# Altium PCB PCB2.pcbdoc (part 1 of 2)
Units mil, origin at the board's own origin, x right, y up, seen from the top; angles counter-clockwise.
Board outline 3822.51 x 2229.86 mil, 2 copper layers (Top Layer, Bottom Layer); 117 components, 92 nets, 474 pads, 260 vias.
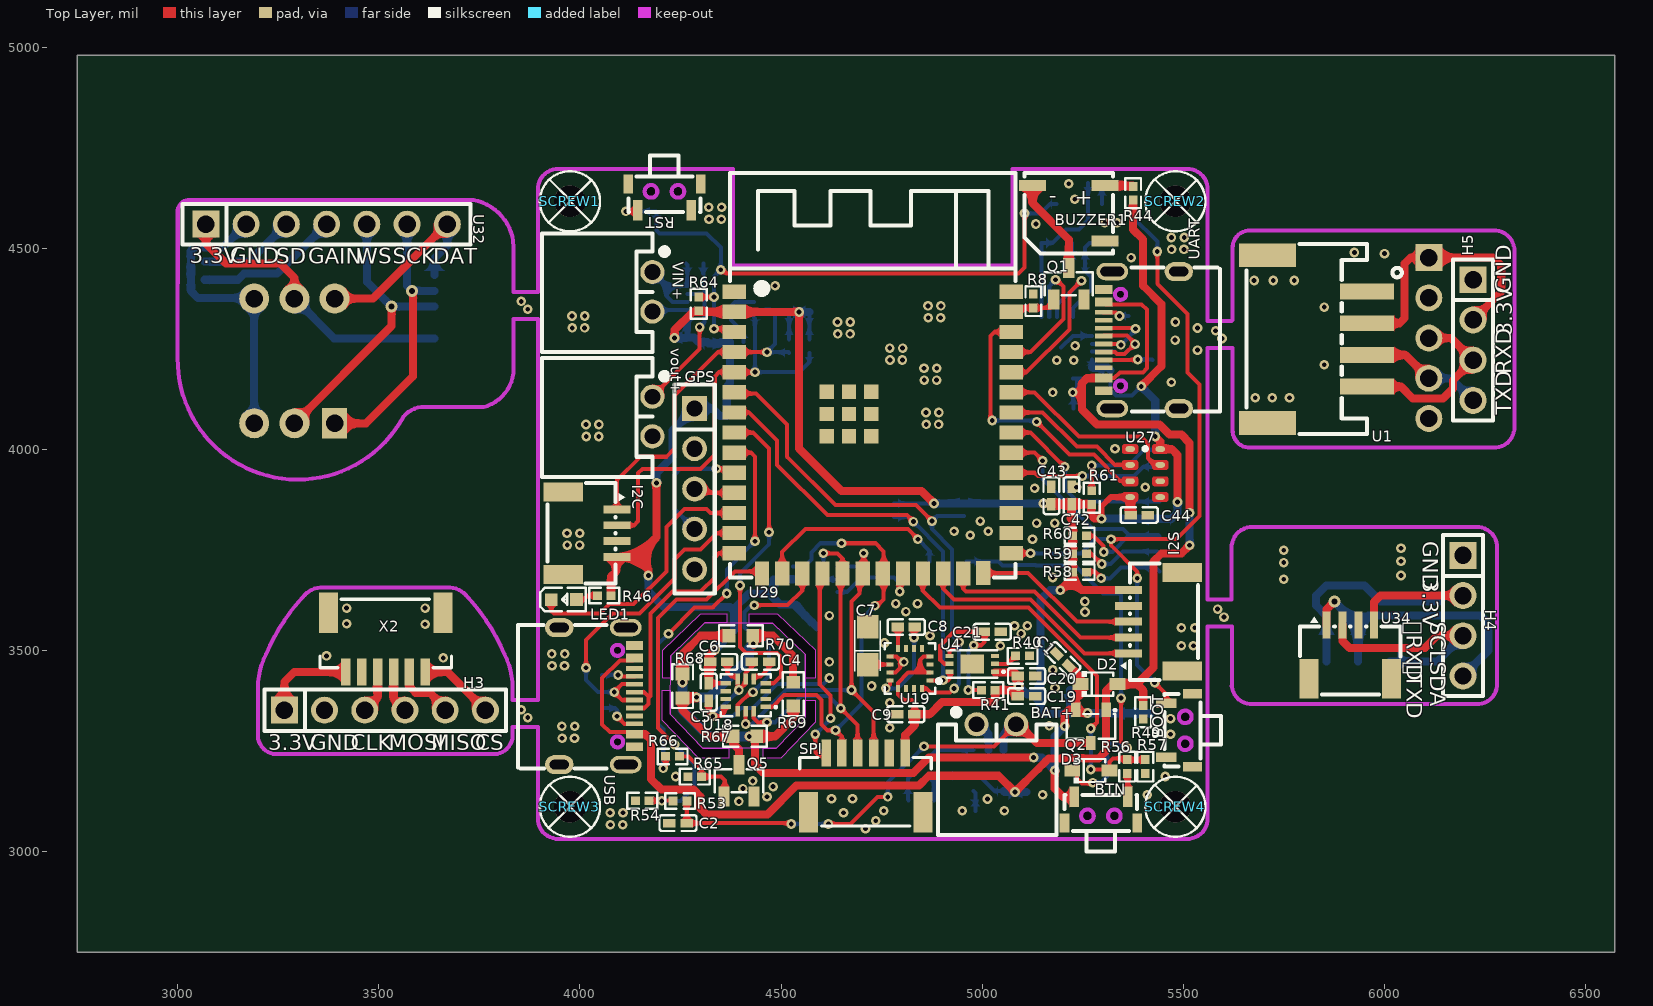
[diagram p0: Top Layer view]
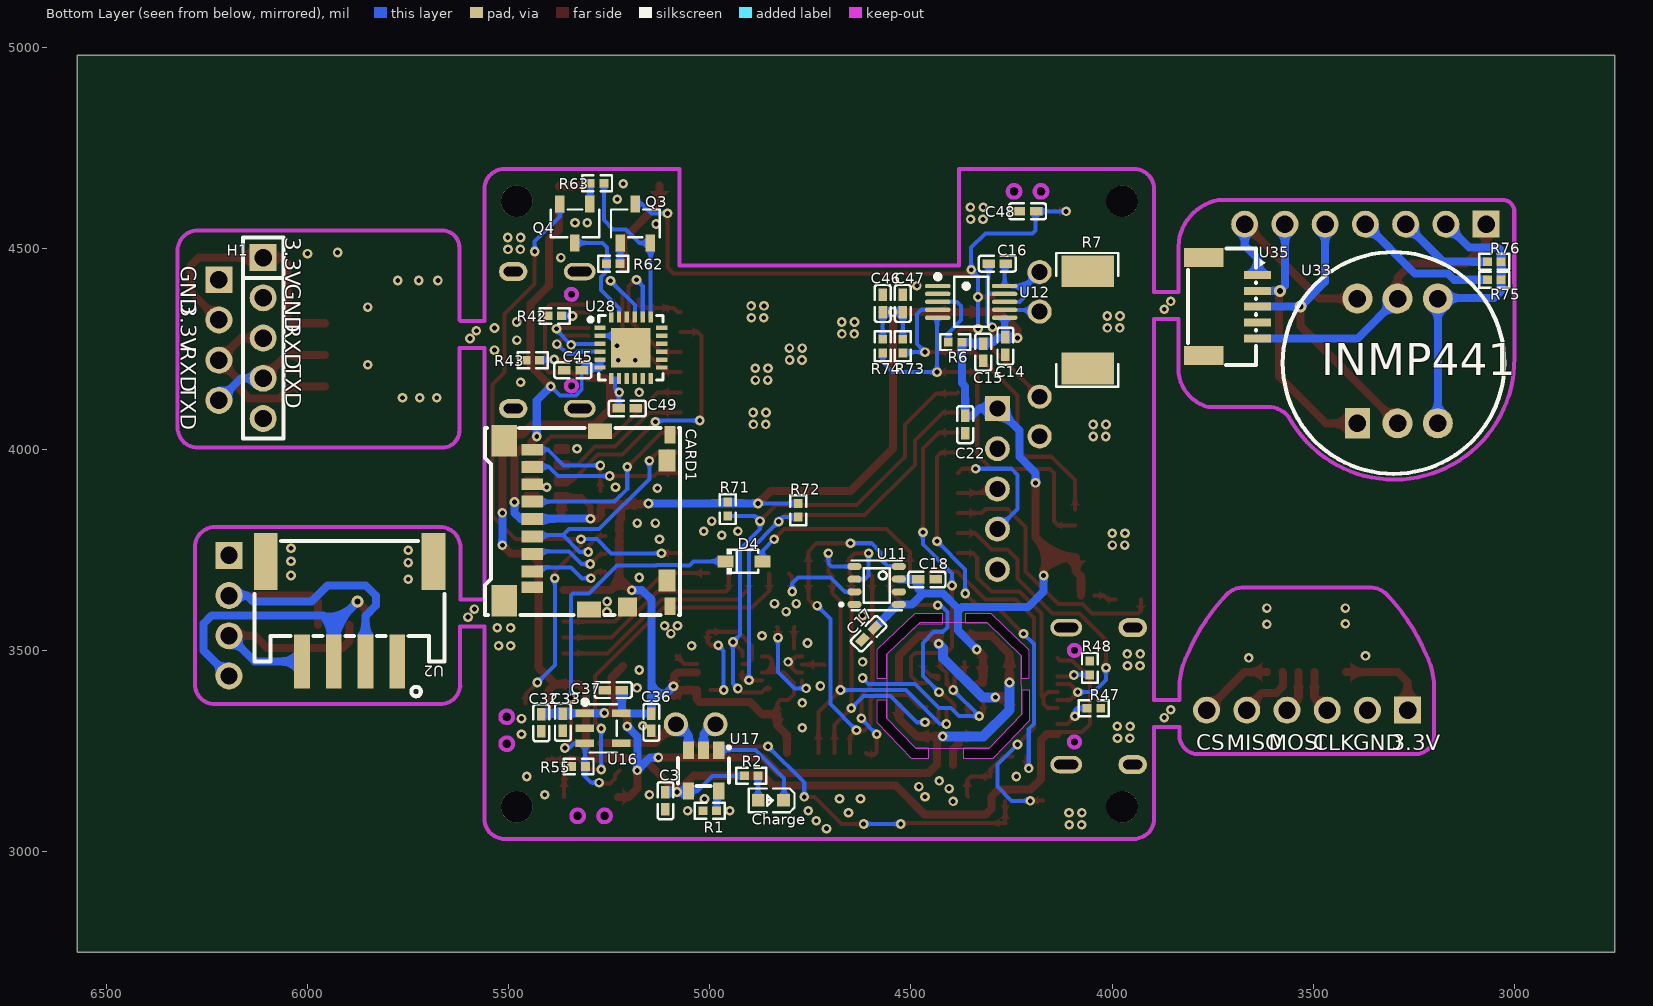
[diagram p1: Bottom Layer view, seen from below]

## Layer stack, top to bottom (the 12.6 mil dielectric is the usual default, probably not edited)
Top Layer: signal copper (thickness not stored)
Dielectric: dielectric 12.6, FR-4, Dk 4.8
Bottom Layer: signal copper (thickness not stored)

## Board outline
6572.51,2750 2750,2750 2750,4979.86 6572.51,4979.86
cut-out: 4365.02,3568.87 4310.07,3568.87 4225.02,3486.31 4225.02,3431.5 4205.12,3431.5 4205.12,3501.11 4300.16,3591.5 4365.02,3591.5
cut-out: 4224.93,3401.5 4224.93,3341.84 4305.21,3256.5 4370.02,3256.5 4370.02,3231.6 4295.16,3231.6 4205.02,3326.38 4205.02,3401.5
cut-out: 4455.12,3256.41 4487.39,3256.41 4560.02,3331.5 4560.02,3376.05 4585.15,3376.05 4585.15,3321.59 4499.51,3231.5 4455.12,3231.5
cut-out: 4560.23,3431.13 4560.23,3491.05 4480.39,3566.4 4420.47,3566.4 4420.47,3591.52 4490.47,3591.52 4585.02,3501.46 4585.02,3431.13

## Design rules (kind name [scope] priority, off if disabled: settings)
Clearance copperThickness1oz [All] p1: gap=7 ignorepadtopadclearanceinfootprint=FALSE except(4: Track-Track; 6: Track-SMDPad SMDPad-SMDPad Track-THPad SMDPad-THPad THPad-THPad Track-Via SMDPad-Via THPad-Via Via-Via SMDPad-Fill THPad-Fill Via-Fill Fill-Fill Track-Region SMDPad-Region THPad-Region Via-Region Region-Region Track-Poly SMDPad-Poly THPad-Poly Via-Poly Fill-Poly Region-Poly Poly-Poly Track-Text SMDPad-Text THPad-Text Via-Text Fill-Text Region-Text Poly-Text Text-Text; 6.9: Track-Hole SMDPad-Hole THPad-Hole Via-Hole Fill-Hole Region-Hole Poly-Hole Text-Hole Sheet-Hole; 11.8: Track-Fill Fill-Region Track-Sheet SMDPad-Sheet THPad-Sheet Via-Sheet Fill-Sheet Region-Sheet Poly-Sheet Text-Sheet)
Clearance copperThickness2oz [All] p1: gap=7 ignorepadtopadclearanceinfootprint=FALSE except(6: Track-SMDPad SMDPad-SMDPad Track-THPad SMDPad-THPad THPad-THPad Track-Via SMDPad-Via THPad-Via Via-Via SMDPad-Fill THPad-Fill Via-Fill Fill-Fill Track-Region SMDPad-Region THPad-Region Via-Region Region-Region Track-Poly SMDPad-Poly THPad-Poly Via-Poly Fill-Poly Region-Poly Poly-Poly Track-Text SMDPad-Text THPad-Text Via-Text Fill-Text Region-Text Poly-Text Text-Text; 6.9: Track-Hole SMDPad-Hole THPad-Hole Via-Hole Fill-Hole Region-Hole Poly-Hole Text-Hole Sheet-Hole; 8: Track-Track; 11.8: Track-Fill Fill-Region Track-Sheet SMDPad-Sheet THPad-Sheet Via-Sheet Fill-Sheet Region-Sheet Poly-Sheet Text-Sheet)
DiffPairsRouting differentialPair [All] p1: maxuncoupledlength=10 maxlimit=5.9843 mostfreqgap=5.9843 toplayer_minwidth=5 toplayer_prefwidth=10 toplayer_maxwidth=100 bottomlayer_minwidth=5 bottomlayer_prefwidth=10 bottomlayer_maxwidth=100
PasteMaskExpansion pasteMaskExpansion [All] p1:
PlaneConnect innerPlane [All] p1: planeconnectstyle=Relief reliefexpansion=20 reliefentries=4 reliefconductorwidth=10 reliefairgap=10
PolygonConnect copperRegion [All] p1: connectstyle=Relief reliefentries=4 reliefconductorwidth=10 polygonreliefangle="90 Angle" airgapwidth=10
PolygonConnect copperRegion1 [All] p1: connectstyle=Direct reliefentries=4 reliefconductorwidth=10 polygonreliefangle="90 Angle" airgapwidth=10
RoutingVias viaSize [All] p1: viastyle="Through Hole" holewidth=12.0078 minholewidth=11.811 maxholewidth=248.0314 width=24.0158 minwidth=19.685 maxwidth=393.7008
SolderMaskExpansion solderMaskExpansion [All] p1: useseparateexpansions=TRUE expansion=2.0079 expansionbottom=2.0079
Width copperThickness1oz [All] p1: maxlimit=100 minlimit=5 preferedwidth=10
Width copperThickness2oz [All] p1: maxlimit=100 minlimit=8 preferedwidth=10

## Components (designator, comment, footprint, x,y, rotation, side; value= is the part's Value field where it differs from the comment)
BAT+ "XH2.54-2P_H弯针插座" CONN-TH_2P-P2.5_XH2.54-2P_H 5035.02,3316.5 r0 top
BOOT "1TS003B-1800-3500A-CT" SW-SMD_1TS003B-XXXX-3500A-CT#1 5490.02,3301.5 r270 top
BTN "1TS003B-1800-3500A-CT" SW-SMD_1TS003B-XXXX-3500A-CT#2 5294.94,3103.36 r180 top
BUZZER1 "MLT-5020" BUZ-SMD_L5.0-W5.5-P4.60 5215.02,4586.5 r180 top
C1 "CL05A106MQ5NUNC" C0402 5200.02,3476.5 r315 top
C2 "CL05A106MQ5NUNC" C0402 4243.64,3070.81 r180 top
C3 "CL05A106MQ5NUNC" C0402 5110.02,3126.5 r90 bottom
C4 "CC0402KRX7R7BB103" C0402 4448.64,3472.02 r180 top
C5 "CC0402KRX7R7BB104" C0402 4320.02,3396.5 r90 top
C6 "GRM155R61E225KE11D" C0402 4345.02,3471.5 r180 top
C7 "TAJA475K016RNJ" CASE-A_3216 4715.02,3511.5 r90 top
C8 "CL05B224KO5NNNC" C0402 4810.89,3558.36 r0 top
C9 "CC0402KRX7R7BB104" C0402 4810.02,3341.5 r0 top
C14 "CC0402KRX7R7BB104" C0402 4265.02,4256.5 r90 bottom
C15 "C1005X5R105KCTS" C0402 4320.02,4241.5 r90 bottom
C16 "CC0402KRX7R7BB104" C0402 4285.02,4461.5 r180 bottom
C17 "CC0402KRX7R7BB104" C0402 4605.02,3541.5 r135 bottom
C18 "C1005X5R105KCTS" C0402 4460.02,3676.5 r0 bottom
C19 "CC0402KRX7R7BB104" C0402 5110.02,3386.5 r180 top
C20 "C1005X5R105KCTS" C0402 5110.02,3436.5 r180 top
C21 "CC0402KRX7R7BB104" C0402 5025.02,3546.5 r180 top
C22 "CC0402KRX7R7BB104" C0402 4365.02,4061.5 r90 bottom
C32 "CL05A106MQ5NUNC" C0402 5418.56,3320.04 r90 bottom
C33 "CC0402KRX7R7BB104" C0402 5365.02,3321.5 r90 bottom
C36 "CL05A106MQ5NUNC" C0402 5145.02,3321.5 r90 bottom
C37 "CC0402KRX7R7BB104" C0402 5240.02,3401.5 r180 bottom
C42 "0603B104K500NT" C0402 5221.88,3884.9 r270 top
C43 "C1005X5R105KCTS" C0402 5171.88,3884.9 r270 top
C44 "CC0402KRX7R7BB104" C0402 5390.02,3836.5 r0 top
C45 "0603B104K500NT" C0402 5340.02,4196.5 r0 bottom
C46 "CC0402KRX7R7BB104" C0402 4570.02,4362.5 r90 bottom
C47 "C1005X5R105KCTS" C0402 4520.02,4362.5 r90 bottom
C48 "C1005X5R105KCTS" C0402 4210.02,4591.5 r0 bottom
C49 "CC0402KRX7R7BB104" C0402 5205.02,4101.5 r0 bottom
CARD1 "TF-110" TF-SMD_TF-110 5304.85,3823.2 r270 bottom
Charge "XL-1608SURC-06" LED0603-RD_RED 4848.02,3127.5 r0 bottom
D2 "1N5819WS_C191023" SOD-323_L1.8-W1.3-LS2.5-RD 5290.02,3416.5 r0 top
D3 "1N5819WS_C191023" SOD-323_L1.8-W1.3-LS2.5-RD 5270.02,3201.5 r0 top
D4 "1N5819WS_C191023" SOD-323_L1.8-W1.3-LS2.5-RD 4915.02,3721.5 r180 bottom
GPS "2.54-1*5P母" HDR-TH_5P-P2.54-V-F 4285.02,3901.5 r270 top
H1 "KH-2.54PH180-1X5P-L11.5" HDR-TH_5P-P2.54-V-M 6109.98,4276.54 r270 bottom
H3 "PZ254V-11-06P" HDR-TH_6P-P2.54-V-M 3515.02,3351.5 r0 top
H4 "PZ254V-11-04P" HDR-TH_4P-P2.54-V-M 6195.02,3586.5 r270 top
H5 "PZ254V-11-04P" HDR-TH_4P-P2.54-V-M 6219.98,4271.54 r270 top
I2C "ZX-SH1.0-4PWT" CONN-SMD_4P-P1.00_MEGASTAR_ZX-SH1.0-4PWT 4025.02,3791.5 r270 top
I2S "ZX-SH1.0-5PWT" CONN-SMD_5P-P1.00_MEGASTAR_ZX-SH1.0-5PWT 5430.02,3571.5 r90 top
LED1 "XL-1608SURC-06" LED0603-RD_RED 3960.02,3626.5 r0 top
Q1 "SI2302-HXY" SOT-23-3_L2.9-W1.3-P1.90-LS2.4-BR 5215.02,4411.5 r270 top
Q2 "AO3401_C727156" SOT-23-3_L2.9-W1.4-P1.90-LS2.6-BR 5270.02,3311.5 r90 top
Q3 "S8050_C181158" SOT-23-3_L2.9-W1.6-P1.90-LS2.8-BR 5185.02,4561.5 r270 bottom
Q4 "S8050_C181158" SOT-23-3_L2.9-W1.6-P1.90-LS2.8-BR 5335.02,4561.5 r90 bottom
Q5 "AO3400A_C20917" SOT-23-3_L2.9-W1.3-P1.90-LS2.4-BR 4395.02,3176.5 r270 top
R1 "0402WGF2001TCE" R0402 5000.02,3101.5 r0 bottom
R2 "0402WGF3300TCE" R0402 4897.02,3188.5 r180 bottom
R6 "RTT02472JTH" R0402 4390.02,4266.5 r0 bottom
R7 "LRAN25EJER005" RES-SMD_L6.4-W3.2-R2512 4060.02,4321.5 r90 bottom
R8 "RC0402FR-0710KL" R0402 5127.02,4368.5 r270 top
R40 "RC0402FR-0710KL" R0402 5100.02,3486.5 r180 top
R41 "0402WGF1001TCE" R0402 5015.02,3401.5 r0 top
R42 "0402WGF5101TCE" R0402 5385.02,4331.5 r0 bottom
R43 "0402WGF5101TCE" R0402 5440.02,4221.5 r0 bottom
R44 "0402WGF220KTCE" R0402 5375.02,4636.5 r270 top
R46 "0402WGF1001TCE" R0402 4060.02,3636.5 r0 top
R47 "0402WGF5101TCE" R0402 4045.02,3356.5 r180 bottom
R48 "0402WGF5101TCE" R0402 4055.02,3456.5 r90 bottom
R49 "0402WGF2003TCE" R0402 5400.02,3346.5 r90 top
R53 "0402WGF5103TCE" R0402 4248.64,3125.81 r0 top
R54 "0402WGF5103TCE" R0402 4155.02,3126.5 r0 top
R55 "RC0402FR-0710KL" R0402 5326.02,3211.5 r180 bottom
R56 "0402WGF2001TCE" R0402 5360.02,3211.5 r90 top
R57 "0402WGF5101TCE" R0402 5405.02,3211.5 r270 top
R58 "RC0402FR-0710KL" R0402 5241.88,3694.9 r0 top
R59 "RC0402FR-0710KL" R0402 5241.88,3739.9 r0 top
R60 "RC0402FR-0710KL" R0402 5241.88,3784.9 r0 top
R61 "RC0402FR-0710KL" R0402 5271.88,3879.9 r90 top
R62 "RC0402FR-0710KL" R0402 5240.02,4461.5 r180 bottom
R63 "RC0402FR-0710KL" R0402 5280.02,4661.5 r0 bottom
R64 "RC0402FR-0710KL" R0402 4295.02,4361.5 r90 top
R65 "RC0402FR-0710KL" R0402 4285.02,3186.5 r180 top
R66 "0402WGJ0101TCE" R0402 4230.02,3236.5 r0 top
R67 "0603WAF510JT5E" R0603 4410.02,3286.5 r0 top
R68 "0603WAF510JT5E" R0603 4255.02,3411.5 r90 top
R69 "0603WAF510JT5E" R0603 4530.02,3391.5 r270 top
R70 "0603WAF510JT5E" R0603 4400.02,3536.5 r180 top
R71 "0402WGJ0472TCE" R0402 4955.02,3851.5 r90 bottom
R72 "0402WGJ0472TCE" R0402 4780.02,3848.5 r90 bottom
R73 "0402WGJ0472TCE" R0402 4520.02,4256.5 r270 bottom
R74 "0402WGJ0472TCE" R0402 4570.02,4256.5 r270 bottom
R75 "0402WGF1003TCE" R0402 3050.02,4421.5 r0 bottom
R76 "0402WGF1003TCE" R0402 3050.02,4466.5 r0 bottom
RST "1TS003B-1800-3500A-CT" SW-SMD_1TS003B-XXXX-3500A-CT#2 4210.02,4626.5 r0 top
SCREW1 "M2螺丝" M2螺丝 3975.02,4616.5 r0 top locked
SCREW2 "M2螺丝" M2螺丝 5480.02,4616.5 r0 top locked
SCREW3 "M2螺丝" M2螺丝 3975.02,3111.5 r0 top locked
SCREW4 "M2螺丝" M2螺丝 5480.02,3111.5 r0 top locked
SPI "AFC10-S06QCA-00" CONN-SMD_AFC10-S06QCA-00 4710.02,3171.5 r0 top
U1 "HY2.0-4P卧贴耐高温" CONN-SMD_C9900014118 5832.52,4274 r270 top
U2 "HY2.0-4P卧贴耐高温" CONN-SMD_C9900014118 5895.02,3596.5 r0 bottom
U4 "BH1750FVI-TR" WSOF-6_L2.6-W1.6-P0.50-TL-EP 4975.02,3466.5 r180 top
U11 "BME680" LGA-8_L3.0-W3.0-P0.80-TR 4585.02,3661.5 r0 bottom
U12 "INA226AIDGSR" MSOP-10_L3.0-W3.0-P0.50-LS5.0-BL 4350.02,4366.5 r270 bottom
U16 "RT9013-33GB" SOT-23-5_L3.0-W1.7-P0.95-LS2.8-BL 5265.02,3306.5 r270 bottom
U17 "TP4054_C668215" TSOT-23-5_L2.9-W1.6-P0.95-LS2.8-BR 5015.02,3201.5 r90 bottom
U18 "ICM-42688-P" LGA-14_L3.0-W2.5-P0.50-TL 4411.81,3389.08 r180 top
U19 "QMC5883L" LGA-16_L3.0-W3.0-P0.50-BL_SQ 4820.11,3455.25 r90 top
U27 "MSM261S4030H0" MSM-MIC 5405.02,3941.5 r180 top
U28 "CH9102F" QFN-24_L4.0-W4.0-P0.50-BL-EP2.5 5196.02,4252.5 r270 bottom
U29 "ESP32-S3-WROOM-1-N16R8" WIRELM-SMD_ESP32-S3-WROOM-1 4727.7,4041.5 r0 top locked
U32 "2.54-1*7P/30mm(3+24+3)" HDR-TH_7P-P2.54-V-M-1 3370.18,4559.66 r0 top
U33 "inmp441" INMP441 3300.18,4214.66 r90 bottom
U34 "ZX-SH1.0-4PWT" CONN-SMD_4P-P1.00_MEGASTAR_ZX-SH1.0-4PWT 5915.02,3496.5 r0 top
U35 "ZX-SH1.0-5PWT" CONN-SMD_5P-P1.00_MEGASTAR_ZX-SH1.0-5PWT 3705.18,4354.66 r270 bottom
UART "TYPE-C 16PIN 2MD(073)" USB-C-SMD_TYPE-C-6PIN-2MD-073 5395.02,4271.5 r90 top locked
USB "TYPE-C 16PIN 2MD(073)" USB-C-SMD_TYPE-C-6PIN-2MD-073 4042.02,3386.5 r270 top
VIN+ "XH2.54-2P_H弯针插座" CONN-TH_2P-P2.5_XH2.54-2P_H 4180.02,4391.5 r270 top
vout+ "XH2.54-2P_H弯针插座" CONN-TH_2P-P2.5_XH2.54-2P_H 4180.02,4081.5 r270 top
X2 "AFC10-S06QCA-00" CONN-SMD_AFC10-S06QCA-00 3516.8,3519.87 r180 top

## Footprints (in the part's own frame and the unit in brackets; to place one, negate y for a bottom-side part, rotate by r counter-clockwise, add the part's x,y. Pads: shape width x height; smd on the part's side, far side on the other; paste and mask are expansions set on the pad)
BUZ-SMD_L5.0-W5.5-P4.60 [mm]
  rect 1.7x0.7 smd: 1(-2.3,-1.75) 2(2.3,-1.75) 3(-2.3,1.75)
  silkscreen extent -2.79,-2.54 2.79,2.54
C0402 [mm]
  rect 0.79x0.54 smd: 1(-0.545,0) 2(0.545,0)
  silkscreen extent -1.17,-0.5 1.17,0.5
CASE-A_3216 [mil]
  rect 59.05x53.5 smd: 1(-47.24,0) 2(47.24,0)
  silkscreen extent -63,-32 63,32
CONN-SMD_4P-P1.00_MEGASTAR_ZX-SH1.0-4PWT [mm]
  rect 0.5x1.7 smd: 1(-1.5,1.7) 2(-0.5,1.7) 3(0.5,1.7) 4(1.5,1.7)
  rect 1.2x2.5 smd: 5(2.6,-1.7) 6(-2.6,-1.7)
  silkscreen extent -3.18,-2.7 3.18,2.21
CONN-SMD_5P-P1.00_MEGASTAR_ZX-SH1.0-5PWT [mm]
  rect 0.5x1.7 smd: 1(-2,1.7) 2(-1,1.7) 3(0,1.7) 4(1,1.7) 5(2,1.7)
  rect 1.2x2.5 smd: 6(3.1,-1.7) 7(-3.1,-1.7)
  silkscreen extent -3.67,-2.7 3.68,2.21
CONN-SMD_AFC10-S06QCA-00 [mm]
  rect 0.6x1.71 smd: 1(-2.5,1.87) 2(-1.5,1.87) 3(-0.5,1.87) 4(0.5,1.87) 5(1.5,1.87) 6(2.5,1.87)
  rect 1.2x2.55 smd: 7(3.61,-1.87) 8(-3.61,-1.87)
  silkscreen extent -4.16,-2.73 4.14,1.59
CONN-SMD_C9900014118 [mm]
  rect 1x3.4 smd: 1(-3,3.15) 2(-1,3.15) 3(1,3.15) 4(3,3.15)
  rect 1.5x3.6 smd: 5(5.3,-3.15) 6(-5.3,-3.15)
  silkscreen extent -6,-4.45 6,5.34
CONN-TH_2P-P2.5_XH2.54-2P_H [mil]
  round 60 hole 39.4: 1(-49.2,0) 2(49.2,0)
  silkscreen extent -145,-275 150,38
HDR-TH_4P-P2.54-V-M [mm]
  rect 1.7x1.7 hole 1.1: 1(-3.81,0)
  round 1.7 hole 1.1: 2(-1.27,0) 3(1.27,0) 4(3.81,0)
  silkscreen extent -5.08,-1.27 5.08,1.27
HDR-TH_5P-P2.54-V-F [mil]
  rect 62x62 hole 40.16: 1(-200,0)
  round 62 hole 40.16: 2(-100,0) 3(0,0) 4(100,0) 5(200,0)
  silkscreen extent -260,-50 260,50
HDR-TH_5P-P2.54-V-M [mm]
  rect 1.7x1.7 hole 1.1: 1(-5.08,0)
  round 1.7 hole 1.1: 2(-2.54,0) 3(0,0) 4(2.54,0) 5(5.08,0)
  silkscreen extent -6.35,-1.27 6.35,1.27
HDR-TH_6P-P2.54-V-M [mm]
  rect 1.7x1.7 hole 1.1: 1(-6.35,0)
  round 1.7 hole 1.1: 2(-3.81,0) 3(-1.27,0) 4(1.27,0) 5(3.81,0) 6(6.35,0)
  silkscreen extent -7.6,-1.3 7.65,1.3
HDR-TH_7P-P2.54-V-M-1 [mm]
  rect 1.7x1.7 hole 1.1: 1(-7.62,0)
  round 1.7 hole 1.1: 2(-5.08,0) 3(-2.54,0) 4(0,0) 5(2.54,0) 6(5.08,0) 7(7.62,0)
  silkscreen extent -9.1,-1.27 9.1,1.27
INMP441 [mm]
  rect 1.9x1.575 hole 1.1: 1(-3.81,2.286)
  round 1.9 hole 1.1: 2(-3.81,-0.254) 3(-3.81,-2.794) 4(4.064,2.286) 5(4.064,-0.254) 6(4.064,-2.794)
  silkscreen extent -7,-7 7,7
LED0603-RD_RED [mm]
  rect 0.8x0.8 smd: 1(-0.8,-0.003) 2(0.8,0.003)
  silkscreen extent -1.49,-0.75 1.39,0.76
LGA-8_L3.0-W3.0-P0.80-TR [mm]
  oval 0.9x0.448 smd: 1(1.4,1.2) 2(1.4,0.4) 3(1.4,-0.4) 4(1.4,-1.2) 5(-1.4,-1.2) 6(-1.4,-0.4) 7(-1.4,0.4) 8(-1.4,1.2)
  silkscreen extent -1.58,-1.58 2.33,1.58
LGA-14_L3.0-W2.5-P0.50-TL [mm]
  rect 0.675x0.28 smd: 1(-1.262,0.75) 2(-1.262,0.25) 3(-1.262,-0.25) 4(-1.262,-0.75) 8(1.262,-0.75) 9(1.262,-0.25) 10(1.262,0.25) 11(1.262,0.75)
  rect 0.28x0.675 smd: 5(-0.5,-1.012) 6(0,-1.012) 7(0.5,-1.012) 12(0.5,1.012) 13(0,1.012) 14(-0.5,1.012)
  silkscreen extent -1.98,-1.33 1.58,1.33
LGA-16_L3.0-W3.0-P0.50-BL_SQ [mm]
  rect 0.25x0.45 smd: 1(-0.75,-1.263) 2(-0.25,-1.263) 3(0.25,-1.263) 4(0.75,-1.263) 9(0.75,1.263) 10(0.25,1.263) 11(-0.25,1.263) 12(-0.75,1.263)
  rect 0.45x0.25 smd: 5(1.263,-0.75) 6(1.263,-0.25) 7(1.263,0.25) 8(1.263,0.75) 13(-1.263,0.75) 14(-1.263,0.25) 15(-1.263,-0.25) 16(-1.263,-0.75)
  silkscreen extent -1.61,-1.95 1.61,1.6
M2螺丝 [mm]
  round 2 hole 2: 1(0,0)
  silkscreen extent -1.9,-1.9 1.9,1.9
MSM-MIC [mil]
  oval 23.64x14.16 smd: 1(-37.4,60.3) 3(-37.4,-19.7) 6(37.4,-19.7) 8(37.4,60.3)
  oval 23.64x14.22 smd: 2(-37.4,20.9) 4(-37.4,-59.1) 5(37.4,-59.1) 7(37.4,20.9)
  Top Layer region: -17.7,-13.8 -17.7,-25.6 -17.7,-25.6 -18.15,-27.86 -19.43,-29.77 -21.34,-31.05 -23.6,-31.5 -23.6,-31.5 -23.6,-31.5 -51.2,-31.5 -51.2,-31.5 -53.46,-31.05 -55.37,-29.77 -56.65,-27.86 -57.1,-25.6 -57.1,-25.6 -57.1,-25.6 -57.1,-13.8 -57.1,-13.8 -56.65,-11.54 -55.37,-9.63 -53.46,-8.35 -51.2,-7.9 -51.2,-7.9 -51.2,-7.9 -23.6,-7.9 -23.6,-7.9 -21.34,-8.35 -19.43,-9.63 -18.15,-11.54 -17.7,-13.8
  Top Layer region: -17.7,-53.1 -17.7,-65 -17.7,-65 -18.15,-67.26 -19.43,-69.17 -21.34,-70.45 -23.6,-70.9 -23.6,-70.9 -23.6,-70.9 -51.2,-70.9 -51.2,-70.9 -53.46,-70.45 -55.37,-69.17 -56.65,-67.26 -57.1,-65 -57.1,-65 -57.1,-65 -57.1,-53.1 -57.1,-53.1 -56.65,-50.84 -55.37,-48.93 -53.46,-47.65 -51.2,-47.2 -51.2,-47.2 -51.2,-47.2 -23.6,-47.2 -23.6,-47.2 -21.34,-47.65 -19.43,-48.93 -18.15,-50.84 -17.7,-53.1
  Top Layer region: -17.7,26.9 -17.7,15 -17.7,15 -18.15,12.74 -19.43,10.83 -21.34,9.55 -23.6,9.1 -23.6,9.1 -23.6,9.1 -51.2,9.1 -51.2,9.1 -53.46,9.55 -55.37,10.83 -56.65,12.74 -57.1,15 -57.1,15 -57.1,15 -57.1,26.9 -57.1,26.9 -56.65,29.16 -55.37,31.07 -53.46,32.35 -51.2,32.8 -51.2,32.8 -51.2,32.8 -23.6,32.8 -23.6,32.8 -21.34,32.35 -19.43,31.07 -18.15,29.16 -17.7,26.9
  Top Layer region: -17.7,66.2 -17.7,54.4 -17.7,54.4 -18.15,52.14 -19.43,50.23 -21.34,48.95 -23.6,48.5 -23.6,48.5 -23.6,48.5 -51.2,48.5 -51.2,48.5 -53.46,48.95 -55.37,50.23 -56.65,52.14 -57.1,54.4 -57.1,54.4 -57.1,54.4 -57.1,66.2 -57.1,66.2 -56.65,68.46 -55.37,70.37 -53.46,71.65 -51.2,72.1 -51.2,72.1 -51.2,72.1 -23.6,72.1 -23.6,72.1 -21.34,71.65 -19.43,70.37 -18.15,68.46 -17.7,66.2
  Top Layer region: 57.1,66.2 57.1,54.4 57.1,54.4 56.65,52.14 55.37,50.23 53.46,48.95 51.2,48.5 51.2,48.5 51.2,48.5 23.6,48.5 23.6,48.5 21.34,48.95 19.43,50.23 18.15,52.14 17.7,54.4 17.7,54.4 17.7,54.4 17.7,54.4 17.7,66.2 17.7,66.2 18.15,68.46 19.43,70.37 21.34,71.65 23.6,72.1 23.6,72.1 23.6,72.1 51.2,72.1 51.2,72.1 53.46,71.65 55.37,70.37 56.65,68.46 57.1,66.2
  Top Layer region: 57.1,26.9 57.1,15 57.1,15 56.65,12.74 55.37,10.83 53.46,9.55 51.2,9.1 51.2,9.1 51.2,9.1 23.6,9.1 23.6,9.1 21.34,9.55 19.43,10.83 18.15,12.74 17.7,15 17.7,15 17.7,15 17.7,15 17.7,26.9 17.7,26.9 18.15,29.16 19.43,31.07 21.34,32.35 23.6,32.8 23.6,32.8 23.6,32.8 51.2,32.8 51.2,32.8 53.46,32.35 55.37,31.07 56.65,29.16 57.1,26.9
  Top Layer region: 57.1,-53.1 57.1,-65 57.1,-65 56.65,-67.26 55.37,-69.17 53.46,-70.45 51.2,-70.9 51.2,-70.9 51.2,-70.9 23.6,-70.9 23.6,-70.9 21.34,-70.45 19.43,-69.17 18.15,-67.26 17.7,-65 17.7,-65 17.7,-65 17.7,-65 17.7,-53.1 17.7,-53.1 18.15,-50.84 19.43,-48.93 21.34,-47.65 23.6,-47.2 23.6,-47.2 23.6,-47.2 51.2,-47.2 51.2,-47.2 53.46,-47.65 55.37,-48.93 56.65,-50.84 57.1,-53.1
  Top Layer region: 57.1,-13.8 57.1,-25.6 57.1,-25.6 56.65,-27.86 55.37,-29.77 53.46,-31.05 51.2,-31.5 51.2,-31.5 51.2,-31.5 23.6,-31.5 23.6,-31.5 21.34,-31.05 19.43,-29.77 18.15,-27.86 17.7,-25.6 17.7,-25.6 17.7,-25.6 17.7,-25.6 17.7,-13.8 17.7,-13.8 18.15,-11.54 19.43,-9.63 21.34,-8.35 23.6,-7.9 23.6,-7.9 23.6,-7.9 51.2,-7.9 51.2,-7.9 53.46,-8.35 55.37,-9.63 56.65,-11.54 57.1,-13.8
  silkscreen extent -4,-64 4,-56
MSOP-10_L3.0-W3.0-P0.50-LS5.0-BL [mm]
  oval 0.28x1.62 smd: 1(-1,-2.11) 2(-0.5,-2.11) 3(0,-2.11) 4(0.5,-2.11) 5(1,-2.11) 6(1,2.11) 7(0.5,2.11) 8(0,2.11) 9(-0.5,2.11) 10(-1,2.11)
  silkscreen extent -1.74,-2.26 1.58,1.07
QFN-24_L4.0-W4.0-P0.50-BL-EP2.5 [mm]
  rect 0.28x0.7 smd: 1(-1.25,-1.95) 2(-0.75,-1.95) 3(-0.25,-1.95) 4(0.25,-1.95) 5(0.75,-1.95) 6(1.25,-1.95) 13(1.25,1.95) 14(0.75,1.95) 15(0.25,1.95) 16(-0.25,1.95) 17(-0.75,1.95) 18(-1.25,1.95)
  rect 0.7x0.28 smd: 7(1.95,-1.25) 8(1.95,-0.75) 9(1.95,-0.25) 10(1.95,0.25) 11(1.95,0.75) 12(1.95,1.25) 19(-1.95,1.25) 20(-1.95,0.75) 21(-1.95,0.25) 22(-1.95,-0.25) 23(-1.95,-0.75) 24(-1.95,-1.25)
  rect 2.5x2.5 smd: 25(0,0)
  silkscreen extent -2.03,-2.67 2.03,2.03
R0402 [mm]
  rect 0.566x0.54 smd: 1(-0.433,0) 2(0.433,0)
  silkscreen extent -0.94,-0.5 0.94,0.5
R0603 [mil]
  rect 31.75x34.02 smd: 1(-29.66,0) 2(29.66,0)
  silkscreen extent -55,-26 55,26
RES-SMD_L6.4-W3.2-R2512 [mm]
  rect 2x3.3 smd: 1(-3.066,0) 2(3.066,0)
  silkscreen extent -4.23,-1.91 4.23,2.01
SOD-323_L1.8-W1.3-LS2.5-RD [mm]
  rect 1x0.75 smd: 1(-1.173,0) 2(1.173,0)
  silkscreen extent -1.08,-0.8 0.9,0.8
SOT-23-3_L2.9-W1.3-P1.90-LS2.4-BR [mm]
  rect 1.25x0.7 smd: 1(1,-0.95) 2(1,0.95) 3(-1,0)
  silkscreen extent -0.73,-1.53 0.73,1.53
SOT-23-3_L2.9-W1.4-P1.90-LS2.6-BR [mm]
  rect 0.91x0.6 smd: 1(1.055,-0.955) 2(1.055,0.955) 3(-1.055,0)
  silkscreen extent -0.78,-1.6 1.09,1.53
SOT-23-3_L2.9-W1.6-P1.90-LS2.8-BR [mm]
  rect 1.07x0.6 smd: 1(1.235,-0.95) 2(1.235,0.95) 3(-1.235,0)
  silkscreen extent -0.88,-1.54 0.88,1.54
SOT-23-5_L3.0-W1.7-P0.95-LS2.8-BL [mm]
  rect 0.49x1.157 smd: 1(-0.95,-1.154) 2(0,-1.154) 3(0.95,-1.154)
  rect 0.49x1.175 smd: 4(0.95,1.154) 5(-0.95,1.154)
  silkscreen extent -1.8,-1.29 1.53,0.85
SW-SMD_1TS003B-XXXX-3500A-CT#1 [mm]
  rect 0.6x1.3 smd: 1(-1.7,-0.825) 2(1.7,-0.825)
  rect 0.6x1.2 smd: 3(2.3,0.825) 4(-2.3,0.825)
  Multi-Layer board cut-out: -0.85,0.77 -1.049,0.715 -1.194,0.569 -1.247,0.37 -1.194,0.171 -1.049,0.025 -0.85,-0.03 -0.85,-0.03 -0.651,0.025 -0.506,0.171 -0.453,0.37 -0.506,0.569 -0.651,0.715 -0.85,0.77
  Multi-Layer board cut-out: 0.85,0.77 0.651,0.715 0.506,0.569 0.453,0.37 0.506,0.171 0.651,0.025 0.85,-0.03 0.85,-0.03 1.049,0.025 1.194,0.171 1.247,0.37 1.194,0.569 1.049,0.715 0.85,0.77
  Multi-Layer keep-out circle w0.254: c-0.85,0.37 r0.4
  Multi-Layer keep-out circle w0.254: c0.85,0.37 r0.4
  silkscreen extent -2.29,-0.94 2.29,2.63
SW-SMD_1TS003B-XXXX-3500A-CT#2 [mm]
  rect 0.6x1.3 smd: 1(-1.7,-0.825) 2(1.7,-0.825)
  rect 0.6x1.2 smd: 3(2.3,0.825) 4(-2.3,0.825)
  Multi-Layer board cut-out: -1.25,0.37 -1.194,0.173 -1.048,0.03 -0.85,-0.023 -0.652,0.03 -0.506,0.173 -0.45,0.37 -0.45,0.37 -0.506,0.567 -0.652,0.711 -0.85,0.763 -1.048,0.71 -1.194,0.567 -1.25,0.37
  Multi-Layer board cut-out: 0.45,0.37 0.506,0.173 0.652,0.03 0.85,-0.023 1.048,0.03 1.194,0.173 1.25,0.37 1.25,0.37 1.194,0.567 1.048,0.711 0.85,0.763 0.652,0.71 0.506,0.567 0.45,0.37
  Multi-Layer keep-out circle w0.254: c-0.85,0.37 r0.4
  Multi-Layer keep-out circle w0.254: c0.85,0.37 r0.4
  silkscreen extent -2.29,-0.94 2.29,2.63
TF-SMD_TF-110 [mil]
  rect 29.5x53.2 smd: 1(126.7,-136) 2(83.4,-136) 3(40.1,-136) 4(-3.2,-136) 5(-46.6,-136) 6(-89.9,-136) 7(-133.2,-136) 8(-175.7,-136) 9(166,-136)
  rect 47.2x47.2 smd: 10(215.2,100.2)
  rect 43.3x27.6 smd: 11(213.2,205.9) 14(-213.1,205.9)
  rect 55.1x43.3 smd: 12(149.4,198.6) 13(-148.9,198.6)
  rect 39.4x59.1 smd: 15(-221.7,32.3) 18(221.7,4.7)
  rect 78.7x63 smd: 16(-198.1,-205.9) 17(199.5,-205.9)
  silkscreen extent -230,-254 235,231
TSOT-23-5_L2.9-W1.6-P0.95-LS2.8-BR [mm]
  rect 1.1x0.7 smd: 1(1.294,-0.951) 2(1.294,-0.001) 3(1.294,0.951) 4(-1.294,0.951) 5(-1.294,-0.949)
  silkscreen extent -0.97,-1.65 1.52,1.61
USB-C-SMD_TYPE-C-6PIN-2MD-073 [mm]
  rect 0.55x1.1 smd: 1(-3.2,2.375) 2(-2.4,2.375) 11(2.4,2.375) 12(3.2,2.375)
  rect 0.3x1.1 smd: 3(-1.75,2.375) 4(-1.25,2.375) 5(-0.75,2.375) 6(-0.25,2.375) 7(0.25,2.375) 8(0.75,2.375) 9(1.25,2.375) 10(1.75,2.375)
  oval 1.2x1.8 hole 0.6 slot 1.2 at 90 deg: 13(-4.325,-2.375) 14(4.325,-2.375)
  oval 1.1x2 hole 0.6 slot 1.5 at 90 deg: 13(-4.325,1.825) 14(4.325,1.825)
  Multi-Layer board cut-out: -2.89,0.955 -2.718,1.004 -2.592,1.132 -2.547,1.305 -2.592,1.478 -2.718,1.606 -2.89,1.655 -2.89,1.655 -3.062,1.606 -3.188,1.478 -3.233,1.305 -3.187,1.132 -3.062,1.004 -2.89,0.955
  Multi-Layer board cut-out: 2.89,0.955 3.062,1.004 3.188,1.132 3.233,1.305 3.188,1.478 3.062,1.606 2.89,1.655 2.89,1.655 2.718,1.606 2.592,1.478 2.547,1.305 2.593,1.132 2.718,1.004 2.89,0.955
  Multi-Layer keep-out circle w0.254: c-2.89,1.305 r0.35
  Multi-Layer keep-out circle w0.254: c2.89,1.305 r0.35
  silkscreen extent -4.5,-4.97 4.57,0.6
WIRELM-SMD_ESP32-S3-WROOM-1 [mm]
  rect 1.5x0.9 smd: 1(-8.75,8.895) 2(-8.75,7.625) 3(-8.75,6.355) 4(-8.75,5.085) 5(-8.75,3.815) 6(-8.75,2.545) 7(-8.75,1.275) 8(-8.75,0.005) 9(-8.75,-1.265) 10(-8.75,-2.535) 11(-8.75,-3.805) 12(-8.75,-5.075) 13(-8.75,-6.345) 14(-8.75,-7.615) 27(8.75,-7.615) 28(8.75,-6.345) 29(8.75,-5.075) 30(8.75,-3.805) 31(8.75,-2.535) 32(8.75,-1.265) 33(8.75,0.005) 34(8.75,1.275) 35(8.75,2.545) 36(8.75,3.815) 37(8.75,5.085) 38(8.75,6.355) 39(8.75,7.625) 40(8.75,8.895)
  rect 0.9x1.5 smd: 15(-6.985,-8.895) 16(-5.715,-8.895) 17(-4.445,-8.895) 18(-3.175,-8.895) 19(-1.905,-8.895) 20(-0.635,-8.895) 21(0.635,-8.895) 22(1.905,-8.895) 23(3.175,-8.895) 24(4.445,-8.895) 25(5.715,-8.895) 26(6.985,-8.865)
  rect 0.9x0.9 smd: 41(-2.9,-0.225) 41(-2.9,1.175) 41(-2.9,2.575) 41(-1.5,-0.225) 41(-1.5,1.175) 41(-1.5,2.575) 41(-0.1,-0.225) 41(-0.1,1.175) 41(-0.1,2.575)
  silkscreen extent -9,-9.14 9.02,16.39
WSOF-6_L2.6-W1.6-P0.50-TL-EP [mm]
  rect 0.505x0.28 smd: 1(-1.427,0.5) 2(-1.427,0) 3(-1.427,-0.5) 4(1.427,-0.5) 5(1.427,0) 6(1.427,0.5)
  rect 1.5x1.2 smd: 7(0,0)
  silkscreen extent -2.05,-0.88 1.58,0.88

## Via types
v1: diameter 24.02, hole 12.01, Top Layer to Bottom Layer, 252 vias
v2: diameter 24, hole 12, Top Layer to Bottom Layer, 5 vias
v3: diameter 30, hole 15, Top Layer to Bottom Layer, 3 vias

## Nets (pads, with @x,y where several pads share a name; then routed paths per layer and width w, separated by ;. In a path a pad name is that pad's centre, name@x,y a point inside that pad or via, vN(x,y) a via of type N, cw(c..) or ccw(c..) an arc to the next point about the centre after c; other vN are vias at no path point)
3.3V: C5.2 C6.2 C9.2 C14.2 C15.2 C17.2 C18.2 C19.2 C20.2 C22.2 C36.2 C37.2 C42.2 C43.2 C44.1 C45.1 C46.1 C47.1 CARD1.4 GPS.1 I2C.4 I2S.5 R6.1 R41.2 R44.2 R46.2 R58.1 R59.1 R60.1 R61.1 R64.1 R71.2 R72.2 R73.1 R74.1 SPI.6 U4.1 U11.6 U11.8 U12.6 U16.5 U18.8 U19.2 U19.4 U19.13 U27.4 U27.8 U28.5 U28.6 U29.2 | length 6936.2
  Top Layer w10: C5.2@4320.02,3417.96 4320.67,3418.61 U18.8@4362.13,3418.61 ; C9.2@4831.48,3341.5 4832.09,3342.11 4832.09,3369.43 4825.02,3376.5 4805.02,3376.5 4790.59,3390.93 U19.13@4790.59,3405.53 4790.59,3419.67 4814.43,3443.51 4814.54,3443.51 4816.46,3445.42 4846,3445.42 ; U19.2@4869.84,3445.42 4846,3445.42 ; U19.4@4869.84,3484.79 4854.45,3484.79 4845.45,3475.79 4845.45,3445.98 4846,3445.42
  Top Layer w15: v1(5296.26,3827.5) 5296.26,3857.74 5319.72,3881.2 U27.8@5367.62,3881.2
  Top Layer w20: R46.2@4077.06,3636.5 4077.06,3683.54 4090.02,3696.5 4090.02,3730.51 I2C.4@4091.95,3732.44 4092.89,3731.5 4140.02,3731.5 ; v1(4170.02,3686.5) 4170.02,3701.5 4140.02,3731.5 ; v1(4190.02,3916.5) 4190.02,3781.5 4140.02,3731.5 ; v1(4235.02,4276.5) 4235.02,4296.5 4280.22,4341.69 U29.2@4383.21,4341.69 4383.4,4341.5 v1(4544.75,4341.5) 4544.75,4001.77 4650.02,3896.5 4848.96,3896.5 v1(4880.02,3865.44) ; C5.2@4320.67,3418.61 4320.67,3486.88 v1(4336.12,3502.33) ; SPI.6@4808.45,3245.12 4808.45,3289.93 4831.48,3312.96 C9.2@4831.48,3341.5 4870.02,3341.5 4900.02,3371.5 5025.02,3371.5 5032.06,3378.54 R41.2@5032.06,3401.5 5073.56,3401.5 C19.2@5088.56,3386.5 5090.01,3387.95 v1(5090.01,3411.13) 5088.56,3412.58 C20.2@5088.56,3436.5 5080.06,3445 U4.1@5031.22,3445 ; v1(5152.25,3865.44) 5169.88,3865.44 C43.2@5171.88,3863.44 C42.2@5220.22,3863.44 ; v1(5193.78,3649.59) 5215.86,3671.68 5224.84,3671.68 ; C42.2@5221.88,3863.44 C42.2@5220.22,3863.44 ; v1(5296.26,3827.5) 5279.28,3827.5 5270.22,3836.57 5270.22,3864.5 5220.22,3864.5 C42.2@5220.22,3863.44 ; I2S.5@5363.09,3650.24 5246.27,3650.24 5224.84,3671.68 ; U27.8@5367.62,3881.2 5368.56,3880.26 C44.1@5368.56,3836.5 ; R44.2@5375.02,4619.46 5375.02,4546.5 5400.02,4521.5 5400.02,4406.5 5445.02,4361.5 5445.02,4206.5 v1(5395.02,4156.5) ; v1(5430.02,4031.64) 5442.42,4019.24 U27.4@5442.42,4000.6 5470.92,4000.6 5485.44,3986.08 v1(5485.44,3868.96) ; C42.2@5220.22,3863.44 5220.22,3826.57 5224.84,3821.94 R60.1@5224.84,3784.9 R59.1@5224.84,3739.9 R58.1@5224.84,3694.9 5224.84,3671.68
  Bottom Layer w9: C45.1@5318.56,4196.5 5318.56,4147.79 5332.49,4133.86 5333.19,4133.86 5333.59,4133.46 5353.7,4133.46 5354.1,4133.86 5372.38,4133.86 v1(5395.02,4156.5)
  Bottom Layer w10: R73.1@4520.02,4273.54 4520.02,4340.04 C47.1@4520.02,4341.04 ; R74.1@4570.02,4273.54 C46.1@4570.02,4341.04 ; R72.2@4780.02,3865.54 4780.12,3865.44 v1(4880.02,3865.44) ; U28.6@5272.8,4203.28 U28.5@5272.8,4222.97
  Bottom Layer w15: C14.2@4265.02,4277.96 4266.95,4279.89 U12.6@4266.95,4327.13
  Bottom Layer w20: v1(4170.02,3686.5) 4170.02,3646.5 4209.04,3607.48 4372.95,3607.48 4376.73,3603.7 ; v1(4190.02,3916.5) 4190.02,3941.5 4230.02,3981.5 4230.02,4046.5 GPS.1@4285.02,4101.5 4330.02,4101.5 4348.56,4082.96 C22.2@4365.02,4082.96 4365.02,4156.5 4372.98,4164.46 R6.1@4372.98,4266.5 4350.02,4266.5 4346.48,4262.96 C15.2@4320.02,4262.96 4316.48,4266.5 4295.02,4266.5 4283.56,4277.96 C14.2@4265.02,4277.96 4263.56,4276.5 v1(4235.02,4276.5) ; v1(4336.12,3502.33) 4383.08,3549.28 4383.08,3597.36 4376.73,3603.7 ; C47.1@4520.02,4340.04 4521.48,4341.5 v1(4544.75,4341.5) 4569.56,4341.5 C46.1@4570.02,4341.04 ; U11.6@4529.9,3677.25 4529.15,3676.5 C18.2@4481.48,3676.5 4481.48,3652.96 4470.02,3641.5 ; C17.2@4589.85,3556.67 4532.26,3614.26 U11.8@4529.9,3614.26 4497.26,3614.26 4470.02,3641.5 ; v1(4880.02,3865.44) v1(5152.25,3865.44) ; v1(5090.01,3411.13) 5109.64,3391.5 5145.02,3391.5 ; v1(5193.78,3649.59) 5168.11,3649.59 5145.02,3626.5 5145.02,3391.5 ; C37.2@5218.56,3401.5 5218.56,3344.94 U16.5@5219.6,3343.9 5218.66,3342.96 C36.2@5145.02,3342.96 5145.02,3391.5 ; U28.6@5272.8,4203.28 5311.77,4203.28 C45.1@5318.56,4196.5 ; v1(5296.26,3827.5) 5439.75,3827.5 CARD1.4@5440.85,3826.4 5469.92,3826.4 5485.02,3841.5 5485.02,3868.54 v1(5485.44,3868.96) ; v1(5395.02,4156.5) 5430.02,4121.5 v1(5430.02,4031.64) ; 4376.73,3603.7 4382.23,3603.7 4420.02,3641.5 4470.02,3641.5
3.3V_EN: D3.1 D4.1 R55.2 U16.3 | length 1053.8
  Top Layer w10: D3.1@5223.85,3201.5 5235.02,3190.33 5235.02,3181.77 5247.36,3169.43 5272.95,3169.43 v1(5275.02,3171.5) ; v1(5345.02,3381.5) 5345.02,3272.76 v1(5360.11,3257.67)
  Bottom Layer w10: D4.1@4961.19,3721.5 5040.02,3721.5 5050.02,3711.5 5079.21,3711.5 5080.05,3712.33 5132.45,3712.33 5133.29,3711.5 5230.02,3711.5 5300.02,3641.5 5340.02,3641.5 5345.02,3636.5 v1(5345.02,3381.5) ; v1(5275.02,3171.5) 5295.02,3171.5 5310.02,3186.5 5310.02,3210.46 R55.2@5308.98,3211.5 ; R55.2@5310.02,3214.46 5310.02,3268.68 U16.3@5310.44,3269.1 5337.42,3269.1 5347.42,3259.1 5358.68,3259.1 v1(5360.11,3257.67) ; R55.2@5310.98,3213.5 R55.2@5312.98,3211.5
$1N4694: R1.1 U17.5 | length 51.3
  Bottom Layer w10: U17.5@4977.66,3150.55 4982.98,3145.23 R1.1@4982.98,3101.5
$1N5288: Charge.1 U17.1 | length 246.4
  Bottom Layer w10: Charge.1@4816.54,3127.63 4815.02,3129.15 4815.02,3181.5 4885.97,3252.44 U17.1@4977.58,3252.44
$1N5387: Charge.2 R2.2 | length 61.3
  Bottom Layer w10: Charge.2@4879.5,3127.36 4879.98,3127.85 R2.2@4879.98,3188.5
$1N6161: C7.1 U19.10 | length 55.7
  Top Layer w10: C7.1@4715.02,3464.26 4715.85,3465.09 U19.10@4770.39,3465.09
$1N6282: C8.1 U19.8 | length 53.9
  Top Layer w10: C8.1@4789.43,3558.36 4790.58,3557.21 U19.8@4790.58,3504.98
$1N9067: R6.2 U12.3 | length 165.5
  Bottom Layer w10: R6.2@4407.06,4266.5 4407.06,4289.46 4375.02,4321.5 4375.02,4356.5 4385.02,4366.5 U12.3@4433.09,4366.5
$1N9978: BUZZER1.2 Q1.3 | length 242
  Top Layer w20: BUZZER1.2@5124.47,4655.39 5124.47,4612.05 5215.02,4521.5 Q1.3@5215.02,4450.87
$1N12524: R40.2 U4.2 | length 60
  Top Layer w10: U4.2@5031.22,3466.49 5062.98,3466.49 R40.2@5082.98,3486.5
$1N12564: C21.2 R41.1 U4.5 | length 390.1
  Top Layer w10: U4.5@4918.82,3466.49 4905.55,3466.49 4895.55,3476.49 4895.55,3512.03 4930.02,3546.5 C21.2@5003.56,3546.5 5005.02,3545.04 5005.02,3521.5 4996.32,3512.8 v1(4979.01,3512.8) ; v1(4965.28,3401.5) R41.1@4997.98,3401.5
  Bottom Layer w10: v1(4965.28,3401.5) 4965.28,3499.07 v1(4979.01,3512.8)
$1N18150: R43.1 UART.4 | length 122.4
  Top Layer w10: UART.4@5301.52,4222.29 5385.81,4222.29 v1(5386.56,4223.04)
  Bottom Layer w10: v1(5386.56,4223.04) 5421.44,4223.04 R43.1@5422.98,4221.5
$1N18154: R42.1 UART.10 | length 66.2
  Top Layer w10: UART.10@5301.52,4340.4 5332.26,4340.4 v1(5341.16,4331.5)
  Bottom Layer w10: v1(5341.16,4331.5) R42.1@5363.98,4331.5
$1N22569: BUZZER1.1 R44.1 | length 70.2
  Top Layer w20: BUZZER1.1@5305.57,4655.39 5373.16,4655.39 R44.1@5375.02,4653.54
$1N23357: LED1.2 R46.1 | length 55.6
  Top Layer w10: LED1.2@3991.5,3626.64 4010.16,3626.64 4020.02,3636.5 R46.1@4042.98,3636.5
$1N23529: C4.1 U18.5 | length 69.9
  Top Layer w10: U18.5@4431.5,3428.94 4431.5,3436.5 4450.02,3436.5 4470.1,3456.58 C4.1@4470.1,3472.02
$1N25668: R48.1 USB.4 | length 82.1
  Top Layer w10: v1(4094.85,3438.84) 4097.99,3435.7 USB.4@4135.52,3435.7
  Bottom Layer w10: R48.1@4055.02,3439.46 4094.24,3439.46 v1(4094.85,3438.84)
$1N25676: R47.1 USB.10 | length 98.4
  Top Layer w10: v1(4092.2,3336.5) 4111.1,3317.59 USB.10@4135.52,3317.59
  Bottom Layer w10: R47.1@4062.06,3356.5 4087.2,3356.5 4092.2,3351.5 v1(4092.2,3336.5)
$1N26665: Q3.1 R62.2 | length 51.6
  Bottom Layer w10: Q3.1@5222.42,4512.87 5222.42,4462.06 R62.2@5222.98,4461.5
$1N26669: Q4.1 R63.2 | length 51.6
  Bottom Layer w10: R63.2@5297.06,4661.5 5297.06,4610.68 Q4.1@5297.62,4610.12
$1N33198: D4.2 U29.16 | length 491.2
  Top Layer w10: U29.16@4502.7,3691.3 4502.7,3744.18 4560.02,3801.5 4814.99,3801.5 v1(4840,3776.48)
  Bottom Layer w10: v1(4840,3776.48) 4868.85,3747.63 D4.2@4868.85,3721.5
$1N33595: BTN.1 R56.1 | length 59.4
  Top Layer w10: R56.1@5360.02,3194.46 5361.87,3192.61 BTN.1@5361.87,3135.84
$1N42658: Q5.1 R65.1 R66.2 | length 188.7
  Top Layer w10: R66.2@4247.06,3236.5 4270.02,3236.5 4302.06,3204.46 R65.1@4302.06,3186.5 4350.02,3186.5 4360.02,3176.5 4360.02,3139.53 Q5.1@4357.62,3137.13
$1N45866: Q5.3 R67.1 R68.1 R69.1 R70.1 | length 711.9
  Top Layer w20: R68.1@4255.02,3381.84 4255.02,3351.5 4320.02,3286.5 R67.1@4380.36,3286.5 4380.36,3268.76 4395.02,3254.1 Q5.3@4395.02,3215.87 ; R70.1@4429.68,3536.5 4480.02,3536.5 4530.02,3486.5 R69.1@4530.02,3421.16
  Top Layer w25: R68.1@4255.02,3381.84 4256.7,3383.51 v1(4290.02,3383.51) ; R70.1@4429.68,3536.5 4430.8,3535.38 v1(4430.8,3516.63)
  Bottom Layer w25: v1(4290.02,3383.51) 4322.04,3383.51 4420.02,3481.5 4420.02,3505.85 v1(4430.8,3516.63)
BUZZER: Q1.1 R8.2 U29.39 | length 125.6
  Top Layer w10: U29.39@5072.19,4341.69 5080.22,4341.69 5090.02,4351.5 R8.2@5127.02,4351.46 ; R8.2@5127.02,4351.46 5169.98,4351.46 5177.62,4359.1 Q1.1@5177.62,4372.13
CS: U18.12 U29.17 | length 527.5
  Top Layer w10: U18.12@4392.13,3349.22 4392.13,3363.87 4424.76,3396.5 v1(4430.02,3396.5) ; v1(4433.02,3612.5) 4516.02,3612.5 4552.7,3649.18 U29.17@4552.7,3691.3
  Bottom Layer w10: v1(4430.02,3396.5) 4470.02,3436.5 4470.02,3518.51 4442.03,3546.5 4420.02,3546.5 4409.49,3557.03 4409.49,3596.07 4425.91,3612.5 v1(4433.02,3612.5)
CS1: U11.2 U29.22 | length 243.9
  Top Layer w10: v1(4795.02,3646.5) 4795.02,3683.63 U29.22@4802.7,3691.3
  Bottom Layer w10: U11.2@4640.14,3645.75 4664.27,3645.75 4700.02,3681.5 4780.02,3681.5 4795.02,3666.5 v1(4795.02,3646.5)
CS2: SPI.1 U29.18 | length 504.7
  Top Layer w10: v1(4585.02,3291.5) 4585.02,3246.5 4590.02,3241.5 4607.98,3241.5 SPI.1@4611.6,3245.12 ; U29.18@4602.7,3691.3 4596,3684.61 4596,3415.51 4623.01,3388.51 v1(4623.01,3331.5)
  Bottom Layer w10: v1(4585.02,3291.5) 4623.01,3329.49 v1(4623.01,3331.5)
D+: 
D-: U28.4 UART.5 UART.7 | length 299.5
  Top Layer w10: UART.5@5301.52,4241.97 5329.54,4241.97 5335,4236.51 5354.04,4236.51 5379.03,4261.5 v2(5380.02,4261.5) 5380.02,4262.48 5360.02,4282.48 5302.65,4282.48 UART.7@5301.52,4281.34
  Bottom Layer w10: U28.4@5272.8,4242.65 5328.86,4242.65 5335,4236.51 5354.04,4236.51 5379.03,4261.5 v2(5380.02,4261.5)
